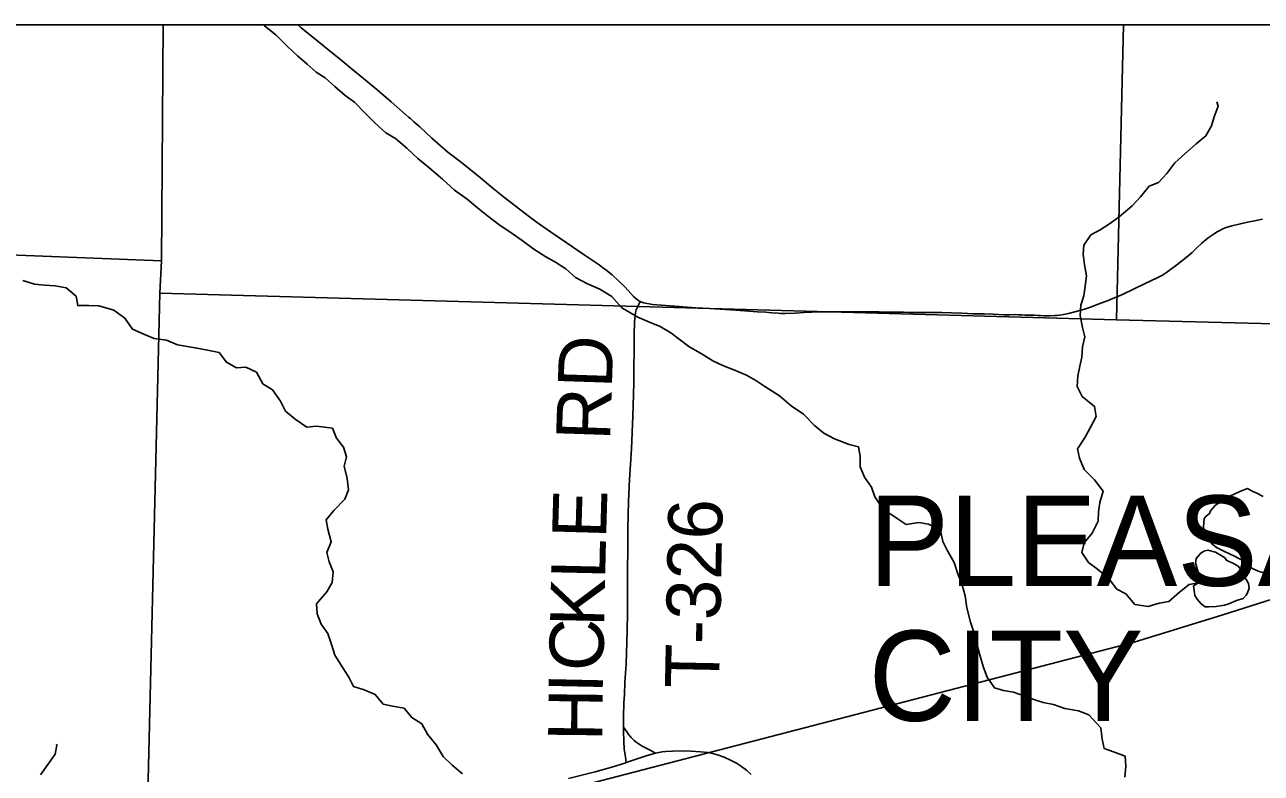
# Model space of a CAD drawing. Extents: x 0 to 34, y 0 to 22.
# Drawn here: x 5.291 to 6.588, y 20.115 to 20.9 of the extents above; entities that cross this region are included whole.
import ezdxf

# ---------------------------------------------------------------- set-up
doc = ezdxf.new("R2010")
doc.units = 0
for name, color, linetype in [('GM_X_Corporation', 7, 'Continuous'), ('GM_X_Corporation_Text', 7, 'Continuous'), ('GM_X_Minor_Lake', 7, 'Continuous'), ('GM_X_Minor_River', 7, 'Continuous'), ('GM_X_Rail_Line', 7, 'Continuous'), ('GM_X_State_Route', 7, 'Continuous'), ('GM_X_Township_Road', 7, 'Continuous'), ('GM_X_Township_Road_Text', 7, 'Continuous'), ('SH_Data', 7, 'Continuous')]:
    doc.layers.add(name, color=color, linetype=linetype)

msp = doc.modelspace()

# ---------------------------------------------------------------- linework, layer by layer
at = {"layer": 'GM_X_Corporation'}
for points in [[(8.9, 20.9), (2.1, 20.9), (2.1, 15.6606)], [(8.9, 20.9), (3.3886, 20.9), (3.3869, 20.7918), (3.3724, 19.7263), (3.3691, 19.5041), (3.3642, 18.7005)]]:
    msp.add_lwpolyline(points, dxfattribs=at)
for points in [[(5.4364, 20.9), (4.4076, 20.9), (4.4032, 20.6929), (5.4344, 20.6525)], [(6.4439, 20.9), (5.4364, 20.9), (5.4344, 20.6525), (5.4328, 20.6183), (6.4366, 20.5905)], [(7.4509, 20.9), (6.4439, 20.9), (6.4366, 20.5905), (7.4437, 20.565)], [(5.4344, 20.6525), (5.4328, 20.6183), (5.4095, 19.6556), (4.3939, 19.6935), (4.4032, 20.6929)]]:
    msp.add_lwpolyline(points, close=True, dxfattribs=at)
at = {"layer": 'GM_X_Minor_Lake'}
for points in [[(6.5906, 20.4052), (6.5838, 20.4086), (6.5788, 20.4108), (6.5739, 20.4134), (6.566, 20.4103), (6.5554, 20.4056), (6.5569, 20.4056), (6.5498, 20.4014), (6.5427, 20.3975), (6.54, 20.3956), (6.5352, 20.3902), (6.534, 20.3872), (6.5303, 20.3841), (6.5284, 20.3822), (6.5277, 20.3735), (6.5285, 20.3693), (6.5286, 20.3667), (6.5301, 20.3622), (6.5358, 20.3562), (6.5415, 20.3517), (6.5484, 20.348), (6.556, 20.3446), (6.5605, 20.3424), (6.57, 20.3372), (6.5784, 20.3301), (6.5852, 20.3267), (6.5924, 20.3249)], [(6.5751, 20.3138), (6.5701, 20.3224), (6.569, 20.3262), (6.5644, 20.3322), (6.5587, 20.3352), (6.5522, 20.3381), (6.55, 20.3411), (6.5465, 20.3434), (6.5405, 20.3467), (6.5325, 20.3489), (6.5283, 20.3477), (6.5246, 20.3454), (6.5201, 20.3401), (6.5197, 20.337), (6.5194, 20.3355), (6.5202, 20.3333), (6.5217, 20.3283), (6.5221, 20.3257), (6.5226, 20.3147)], [(6.5226, 20.3147), (6.5173, 20.3113), (6.5181, 20.3067), (6.5189, 20.3014), (6.5212, 20.2973), (6.5254, 20.2924), (6.5296, 20.2894), (6.5334, 20.2894), (6.5413, 20.2899), (6.55, 20.2911), (6.5545, 20.2927), (6.5624, 20.2962), (6.5696, 20.2982), (6.5726, 20.3016), (6.5737, 20.3035), (6.5759, 20.3085), (6.5751, 20.3138)]]:
    msp.add_lwpolyline(points, dxfattribs=at)
at = {"layer": 'GM_X_Minor_River'}
for points in [[(5.6062, 20.8442), (5.5967, 20.8502), (5.5872, 20.8588), (5.5773, 20.8674), (5.5666, 20.8771), (5.5544, 20.8895), (5.5426, 20.8988), (5.5414, 20.9)], [(6.4454, 20.1108), (6.4464, 20.1222), (6.4455, 20.1328), (6.4334, 20.1372), (6.4236, 20.1409), (6.4216, 20.1507), (6.4203, 20.1625), (6.4074, 20.1763), (6.3967, 20.1804), (6.3824, 20.1829), (6.3706, 20.1869), (6.3596, 20.1891), (6.3498, 20.1924), (6.3403, 20.1957), (6.3285, 20.1998), (6.3179, 20.2015), (6.3085, 20.2045), (6.3008, 20.2158), (6.2969, 20.2259), (6.2934, 20.2376), (6.2895, 20.252), (6.2868, 20.263), (6.2833, 20.2735), (6.2794, 20.2883), (6.2778, 20.3011), (6.2742, 20.3136), (6.27, 20.3242), (6.2661, 20.3359), (6.2592, 20.3483), (6.2542, 20.3581), (6.2518, 20.3694), (6.2393, 20.3761), (6.2291, 20.3779), (6.2159, 20.3759), (6.2064, 20.3822), (6.1915, 20.3923), (6.1831, 20.4047), (6.1796, 20.4149), (6.1723, 20.4254), (6.1677, 20.4364), (6.1676, 20.4474), (6.166, 20.4572), (6.1562, 20.4597), (6.1406, 20.4656), (6.1296, 20.4716), (6.1197, 20.4798), (6.1083, 20.4914), (6.0953, 20.5004), (6.0828, 20.5109), (6.0676, 20.5206), (6.058, 20.5269), (6.0482, 20.5325), (6.0349, 20.538), (6.0243, 20.5421), (6.0129, 20.5476), (6.0019, 20.5543), (5.9878, 20.5625), (5.9688, 20.5767), (5.9578, 20.5834), (5.9464, 20.5879), (5.9342, 20.5934), (5.9175, 20.6031), (5.9072, 20.6151), (5.8943, 20.6225), (5.8814, 20.6281), (5.8689, 20.6348), (5.8586, 20.6441), (5.8479, 20.6509), (5.8377, 20.6564), (5.8251, 20.6646), (5.8129, 20.6736), (5.8023, 20.6811), (5.7886, 20.6904), (5.7764, 20.6997), (5.7661, 20.708), (5.7551, 20.7169), (5.7418, 20.7266), (5.7292, 20.7379), (5.7151, 20.7502), (5.7033, 20.7596), (5.6919, 20.7704), (5.6801, 20.7806), (5.6698, 20.7865), (5.6588, 20.7966), (5.6481, 20.8071), (5.637, 20.8188), (5.6271, 20.8258), (5.6165, 20.8352), (5.6062, 20.8442)], [(6.5226, 20.3147), (6.5128, 20.3127), (6.5026, 20.3047), (6.4914, 20.2951), (6.4812, 20.2934), (6.4699, 20.2899), (6.4559, 20.2917), (6.4463, 20.3029), (6.4368, 20.3081), (6.428, 20.3194), (6.4166, 20.3291), (6.4071, 20.3358), (6.4002, 20.3464), (6.4028, 20.3566), (6.411, 20.3666), (6.4173, 20.3792), (6.4176, 20.389), (6.419, 20.3989), (6.4227, 20.4107), (6.4135, 20.4227), (6.4025, 20.4336), (6.3978, 20.4453), (6.3955, 20.4551), (6.4037, 20.4673), (6.4089, 20.4772), (6.4152, 20.489), (6.4136, 20.4996), (6.4007, 20.5101), (6.3953, 20.5206), (6.3959, 20.5316), (6.3981, 20.5419), (6.4003, 20.5514), (6.401, 20.562), (6.4035, 20.5726), (6.4008, 20.5824), (6.3984, 20.5949), (6.3991, 20.6059), (6.4024, 20.6158), (6.4038, 20.6257), (6.4052, 20.6367), (6.4029, 20.648), (6.4016, 20.6594), (6.4023, 20.6689), (6.4098, 20.6795), (6.4196, 20.6849), (6.4293, 20.6911), (6.4395, 20.6984), (6.453, 20.7099), (6.4616, 20.7195), (6.4709, 20.7306), (6.4807, 20.7345), (6.4893, 20.744), (6.4976, 20.7551), (6.5084, 20.7647), (6.5201, 20.7751), (6.5302, 20.7835), (6.5362, 20.7938), (6.5391, 20.8033), (6.5432, 20.8147), (6.542, 20.8192)], [(5.7502, 20.1144), (5.7395, 20.1234), (5.73, 20.1324), (5.7227, 20.1448), (5.7135, 20.1557), (5.7078, 20.1666), (5.6971, 20.1733), (5.6891, 20.1831), (5.677, 20.1853), (5.6671, 20.1874), (5.6587, 20.1976), (5.6473, 20.2024), (5.636, 20.2057), (5.631, 20.2155), (5.6248, 20.2253), (5.6164, 20.2388), (5.6129, 20.2498), (5.609, 20.2615), (5.6021, 20.2712), (5.5979, 20.2822), (5.597, 20.2924), (5.6079, 20.305), (5.6135, 20.3149), (5.6145, 20.3263), (5.6106, 20.3365), (5.6079, 20.3463), (5.6127, 20.3577), (5.6092, 20.371), (5.6072, 20.3808), (5.6155, 20.3903), (5.6267, 20.4022), (5.6308, 20.4121), (5.6292, 20.4242), (5.626, 20.4371), (5.6286, 20.4466), (5.6255, 20.4568), (5.6182, 20.4665), (5.614, 20.4767), (5.5973, 20.4788), (5.5871, 20.478), (5.5749, 20.4862), (5.5647, 20.4948), (5.5593, 20.5053), (5.5508, 20.517), (5.541, 20.5233), (5.5341, 20.5354), (5.523, 20.5409), (5.5132, 20.5401), (5.5026, 20.546), (5.4949, 20.5562), (5.4828, 20.5587), (5.4699, 20.5612), (5.4514, 20.5644), (5.4396, 20.5692), (5.4268, 20.571), (5.4158, 20.5754), (5.404, 20.5806), (5.396, 20.5923), (5.3846, 20.6005), (5.3686, 20.6052), (5.3584, 20.6055), (5.3467, 20.6054), (5.3451, 20.6152), (5.3344, 20.6242), (5.3231, 20.626), (5.3117, 20.627), (5.3011, 20.628), (5.289, 20.6317)], [(5.3075, 20.1132), (5.3154, 20.1242), (5.3228, 20.1349), (5.3247, 20.1444), (5.3243, 20.1455)]]:
    msp.add_lwpolyline(points, dxfattribs=at)
at = {"layer": 'GM_X_Rail_Line'}
msp.add_lwpolyline([(7.1041, 20.4576), (6.548, 20.2811), (6.4552, 20.2522), (5.6204, 20.0355), (5.1742, 19.9198), (4.9387, 19.8589), (4.9007, 19.8493), (4.8622, 19.8368), (4.8204, 19.8197), (4.7961, 19.8057), (4.7682, 19.7883), (4.6322, 19.6788), (3.9277, 19.0962), (3.874, 19.0476), (3.8339, 19.0097), (3.7908, 18.9611), (3.75, 18.9158), (3.7169, 18.8748), (3.6829, 18.8279), (3.1625, 18.0833)], dxfattribs=at)
at = {"layer": 'GM_X_State_Route'}
msp.add_lwpolyline([(5.8614, 20.1094), (5.8897, 20.1165), (5.907, 20.1214), (5.9207, 20.1256), (5.9221, 20.1261), (5.9295, 20.1285), (5.9442, 20.1336), (5.953, 20.136), (5.96, 20.1374), (5.9638, 20.1378), (5.9706, 20.1382), (5.9794, 20.1383), (5.99, 20.1381), (6.0001, 20.1375), (6.008, 20.1365), (6.0142, 20.1352), (6.019, 20.1339), (6.0249, 20.1317), (6.0324, 20.1283), (6.0379, 20.1253), (6.0432, 20.1219), (6.0482, 20.1181), (6.0532, 20.1134)], dxfattribs=at)
at = {"layer": 'GM_X_Township_Road'}
for points in [[(5.5774, 20.9), (5.5811, 20.8969), (5.5898, 20.8898), (5.5989, 20.8824), (5.6101, 20.8734), (5.6226, 20.8632), (5.6332, 20.8546), (5.6465, 20.8435), (5.6605, 20.832), (5.6756, 20.8191), (5.6904, 20.8059), (5.6937, 20.8031), (5.6956, 20.8015), (5.6994, 20.7983), (5.7054, 20.7929), (5.7181, 20.7811), (5.7269, 20.7732), (5.7351, 20.7665), (5.7492, 20.7554), (5.7691, 20.7394), (5.7825, 20.7283), (5.7946, 20.7186), (5.8148, 20.703), (5.8208, 20.6984), (5.8275, 20.6933), (5.8427, 20.6826), (5.8525, 20.6761), (5.8792, 20.6579), (5.8936, 20.6482), (5.8974, 20.6455), (5.9006, 20.643), (5.9073, 20.6375), (5.9147, 20.6308), (5.921, 20.6248), (5.9297, 20.6151), (5.9321, 20.6127), (5.9338, 20.6114), (5.9354, 20.6103), (5.9368, 20.6096)], [(5.9368, 20.6096), (5.9384, 20.6089), (5.9404, 20.6083), (5.9425, 20.6079), (5.9498, 20.6067), (5.9591, 20.6057), (5.9777, 20.6044), (5.9814, 20.6041), (5.995, 20.6031), (6.0099, 20.6023), (6.026, 20.6013), (6.0371, 20.6006), (6.06, 20.5989), (6.0686, 20.5984), (6.0748, 20.5979), (6.0816, 20.5973), (6.0841, 20.5972), (6.089, 20.5972), (6.0995, 20.5976), (6.1088, 20.5982), (6.1243, 20.5987), (6.1373, 20.599), (6.1546, 20.5989), (6.1638, 20.5989), (6.1723, 20.5988), (6.176, 20.5988), (6.1784, 20.5988), (6.1815, 20.5988), (6.1845, 20.5987), (6.1876, 20.5988), (6.1912, 20.5986), (6.1943, 20.5986), (6.1973, 20.5985), (6.2003, 20.5986), (6.204, 20.5985), (6.2107, 20.5985), (6.2132, 20.5985), (6.2193, 20.5982), (6.2311, 20.5983), (6.2534, 20.5982), (6.2633, 20.5979), (6.2744, 20.5975), (6.2862, 20.5968), (6.2936, 20.5966), (6.2978, 20.5966), (6.307, 20.5963), (6.3187, 20.5958), (6.3248, 20.5957), (6.3304, 20.5959), (6.3341, 20.5958), (6.3371, 20.5958), (6.3408, 20.5955), (6.3439, 20.5955), (6.3469, 20.5953), (6.3506, 20.5952), (6.3537, 20.595), (6.3568, 20.5949), (6.3605, 20.5947), (6.3666, 20.5946), (6.3718, 20.5949), (6.3743, 20.5951), (6.377, 20.5954), (6.3811, 20.5961), (6.3861, 20.5972), (6.3982, 20.6001), (6.4041, 20.6019), (6.4094, 20.6038), (6.4175, 20.6068), (6.4278, 20.6108), (6.4437, 20.6175), (6.466, 20.6281), (6.4794, 20.6345), (6.4848, 20.6374), (6.489, 20.6401), (6.5, 20.6482), (6.5098, 20.6559), (6.5159, 20.6612), (6.5213, 20.6663), (6.5257, 20.6706), (6.5309, 20.6751), (6.5339, 20.6773), (6.5389, 20.6808), (6.5416, 20.6825), (6.5443, 20.6839), (6.5482, 20.6858), (6.5516, 20.6872), (6.5575, 20.6891), (6.5666, 20.6913), (6.5739, 20.6928), (6.5812, 20.6943), (6.5897, 20.696)], [(5.9192, 20.1632), (5.9192, 20.174), (5.9197, 20.1889), (5.9202, 20.1976), (5.9207, 20.21), (5.9219, 20.2298), (5.9226, 20.2522), (5.9232, 20.2646), (5.9234, 20.2832), (5.9236, 20.3317), (5.9237, 20.346), (5.9238, 20.3715), (5.9245, 20.4001), (5.9257, 20.4231), (5.9275, 20.4553), (5.9291, 20.4895), (5.9295, 20.5007), (5.9299, 20.5124), (5.93, 20.5242), (5.9302, 20.5417), (5.9305, 20.5572), (5.9306, 20.5746), (5.9309, 20.5883), (5.9314, 20.5946), (5.932, 20.5983), (5.9327, 20.6008), (5.9339, 20.6038), (5.935, 20.606), (5.9368, 20.6096)], [(5.9221, 20.1261), (5.9213, 20.1317), (5.9201, 20.1404), (5.9195, 20.1484), (5.9192, 20.159), (5.9192, 20.1632)], [(5.953, 20.136), (5.9474, 20.139), (5.9436, 20.141), (5.941, 20.1423), (5.9388, 20.1434), (5.9367, 20.1447), (5.9347, 20.146), (5.9326, 20.1476), (5.9306, 20.1491), (5.9274, 20.1523), (5.925, 20.1551), (5.9227, 20.1582), (5.9192, 20.1632)]]:
    msp.add_lwpolyline(points, dxfattribs=at)
at = {"layer": 'SH_Data'}
msp.add_line((2.1, 20.9), (8.9, 20.9), dxfattribs=at)

# ---------------------------------------------------------------- texts
at = {"layer": 'GM_X_Corporation_Text'}
for s, p in [('PLEASANT', (6.1765, 20.3114)), ('CITY', (6.1765, 20.1698))]:
    msp.add_text(s, height=0.0947, rotation=0, dxfattribs=at).set_placement(p)
at = {"layer": 'GM_X_Township_Road_Text'}
for s, height, rotation, p in [('RD', 0.05682, 88.1088, (5.9052, 20.4634)), ('E', 0.0568, 88.3369, (5.901, 20.3606)), ('T-326', 0.05682, 88.8743, (6.0195, 20.2035)), ('L', 0.0568, 88.7271, (5.9, 20.3182)), ('K', 0.0568, 88.7395, (5.8989, 20.2682)), ('C', 0.0568, 88.7431, (5.8979, 20.2216)), ('I', 0.0568, 88.79, (5.8974, 20.1983)), ('H', 0.0568, 89.3625, (5.8969, 20.1484))]:
    msp.add_text(s, height=height, rotation=rotation, dxfattribs=at).set_placement(p)

doc.saveas('drawing.dxf')
